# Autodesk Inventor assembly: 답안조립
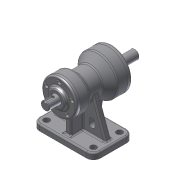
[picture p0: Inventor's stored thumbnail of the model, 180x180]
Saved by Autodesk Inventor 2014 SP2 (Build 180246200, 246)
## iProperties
Created: 2012-11
Part Number: 답안조립
Document SubType Name: Assembly
Designer: 손기택
Author: 손기택
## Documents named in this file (8)
- C:\Users\201-15\Documents\Inventor\450805V1040\답안조립.iam
- C:\Users\201-15\Documents\Inventor\450805V1040\본체.ipt
- C:\Users\201-15\Documents\Inventor\450805V1040\앞커버.ipt
- C:\Users\201-15\Documents\Inventor\450805V1040\뒤커버.ipt
- C:\Users\201-15\Documents\Inventor\450805V1040\베어링 6203.ipt
- C:\Users\201-15\Documents\Inventor\450805V1040\베어링 6205.ipt
- C:\Users\201-15\Documents\Inventor\450805V1040\축.ipt
- C:\Users\201-15\Documents\Inventor\450805V1040\M4x0.5.ipt
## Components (6 placed, 1 different names)
1. M4x0.5:3
2. M4x0.5:7
3. M4x0.5:8
4. M4x0.5:9
5. M4x0.5:11
6. M4x0.5:12
